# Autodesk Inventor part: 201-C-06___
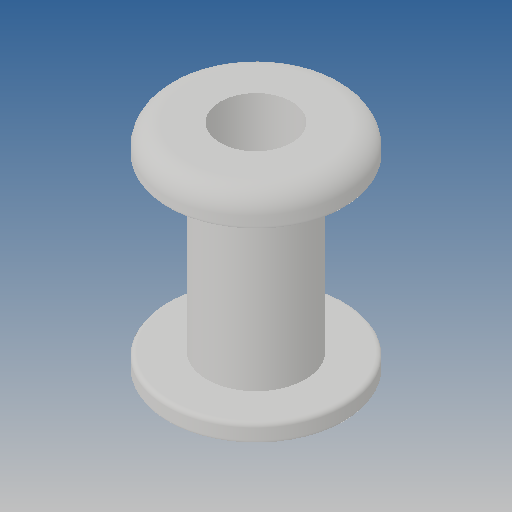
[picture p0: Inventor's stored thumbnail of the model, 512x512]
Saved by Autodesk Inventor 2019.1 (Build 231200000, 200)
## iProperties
Created: 2010-06
Part Number: 201-C-06___
Material: Ogólny
Document SubType Name: Modeling
Designer: CADENGINEERING4
Density: 1 g/cm^3
Appearance: Domyślna
Author: CADENGINEERING4
Revision Number: ANY
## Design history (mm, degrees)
feature "NONE"
node "Bryła1"
